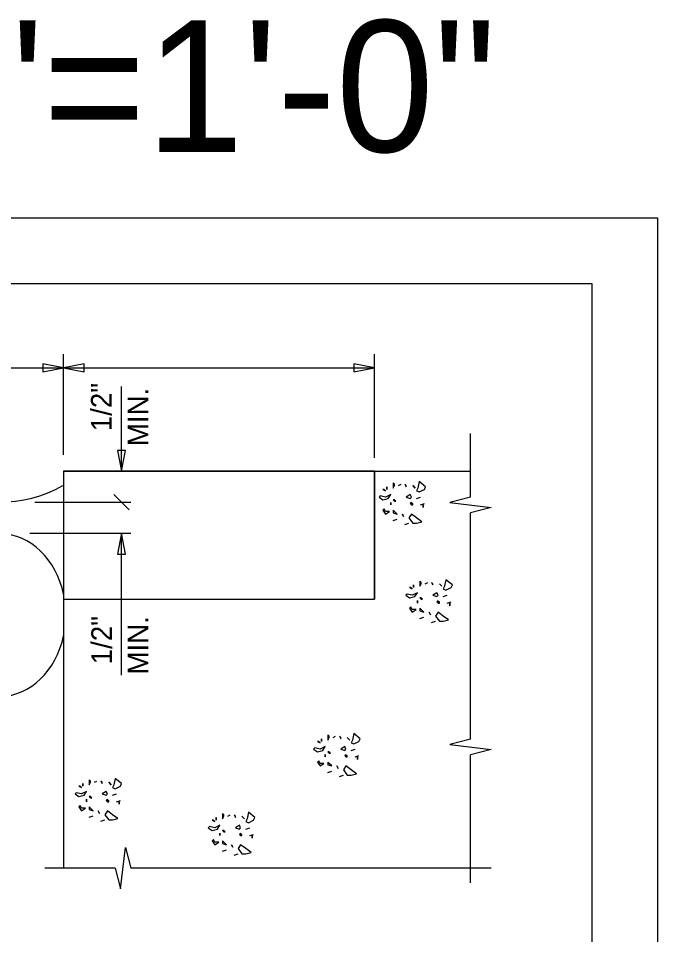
# Model space of a CAD drawing. Extents: x 0 to 11.3, y 0 to 7.8.
# Drawn here: x 9.714 to 11.333, y 5.517 to 7.838 of the extents above; entities that cross this region are included whole.
import ezdxf

# ---------------------------------------------------------------- set-up
doc = ezdxf.new("R2010")
doc.units = 0
for name, color, linetype in [('BORDER_ANNO_Cutsheet', 7, 'Continuous'), ('BRDG_ANNO_Anno-Sheet', 7, 'Continuous'), ('BRDG_ANNO_General-Notes', 7, 'Continuous'), ('BRDG_BASE_Obj-Line', 7, 'Continuous'), ('BRDG_BASE_Pattern', 7, 'Continuous')]:
    doc.layers.add(name, color=color, linetype=linetype)

msp = doc.modelspace()

# ---------------------------------------------------------------- linework, layer by layer
at = {"layer": 'BORDER_ANNO_Cutsheet'}
msp.add_lwpolyline([(0, 7.3333), (11.3333, 7.3333), (11.3333, 0), (0, 0)], close=True, dxfattribs=at)
at = {"layer": 'BRDG_ANNO_Anno-Sheet'}
msp.add_lwpolyline([(0.5, 7.1667), (11.1667, 7.1667), (11.1667, 0.1667), (0.5, 0.1667)], close=True, dxfattribs=at)
at = {"layer": 'BRDG_ANNO_General-Notes'}
for p, q in [((9.8291, 6.7329), (9.8291, 6.9872)), ((10.6164, 6.7246), (10.6164, 6.9872)), ((9.5051, 6.9529), (9.8291, 6.9529)), ((9.829, 6.953), (9.7765, 6.9628)), ((9.7765, 6.9628), (9.7765, 6.9431)), ((9.7765, 6.9431), (9.829, 6.953)), ((9.8815, 6.9628), (9.829, 6.953)), ((9.829, 6.953), (9.8815, 6.9431)), ((9.8291, 6.9529), (10.6164, 6.9529)), ((9.8815, 6.9431), (9.8815, 6.9628)), ((10.6162, 6.953), (10.5638, 6.9628)), ((10.5638, 6.9628), (10.5638, 6.9431)), ((10.5638, 6.9431), (10.6162, 6.953)), ((9.9756, 6.6912), (9.9756, 6.906)), ((9.9855, 6.7437), (9.9658, 6.7437)), ((9.9658, 6.7437), (9.9756, 6.6912)), ((9.9756, 6.6912), (9.9855, 6.7437)), ((9.9756, 6.6125), (9.9563, 6.6318)), ((9.7565, 6.6125), (9.9989, 6.6125)), ((9.995, 6.5931), (9.9756, 6.6125)), ((9.7437, 6.5337), (9.9989, 6.5337)), ((9.9756, 6.5337), (9.9658, 6.4813)), ((9.9756, 6.1746), (9.9756, 6.5337)), ((9.9855, 6.4813), (9.9756, 6.5337)), ((9.9658, 6.4813), (9.9855, 6.4813))]:
    msp.add_line(p, q, dxfattribs=at)
at = {"layer": 'BRDG_BASE_Obj-Line'}
for p, q in [((10.8597, 6.6253), (10.8597, 6.7864)), ((9.829, 6.6912), (10.6654, 6.6912)), ((9.8291, 6.6912), (10.8598, 6.6912)), ((9.8291, 6.6912), (9.8291, 5.6855)), ((10.6164, 6.6912), (10.6164, 6.3671)), ((10.8597, 6.6253), (10.8072, 6.6121)), ((10.8072, 6.6121), (10.9121, 6.599)), ((10.9121, 6.599), (10.8597, 6.5859)), ((10.8597, 6.0122), (10.8597, 6.5859)), ((9.8291, 6.3671), (10.6164, 6.3671)), ((10.8597, 6.0122), (10.8072, 5.9991)), ((10.8072, 5.9991), (10.9121, 5.9859)), ((10.9121, 5.9859), (10.8597, 5.9728)), ((10.8597, 5.6484), (10.8597, 5.9728)), ((9.973, 5.633), (9.9861, 5.738)), ((9.9861, 5.738), (9.9993, 5.6855)), ((9.9599, 5.6855), (9.7818, 5.6855)), ((9.9599, 5.6855), (9.973, 5.633)), ((10.9121, 5.6855), (9.9993, 5.6855))]:
    msp.add_line(p, q, dxfattribs=at)
msp.add_arc((9.666, 6.9425), 0.3299, 240.6646, 299.3018, dxfattribs=at)
for start_param, end_param in [(4.971289, 7.548008), (1.87677, 4.453489)]:
    msp.add_ellipse((9.666, 6.3267), major_axis=(0, 0.2063), ratio=0.818182, start_param=start_param, end_param=end_param, dxfattribs=at)
at = {"layer": 'BRDG_BASE_Pattern'}
for p, q in [((10.6769, 6.6548), (10.6835, 6.6581)), ((10.7229, 6.622), (10.7327, 6.6253)), ((10.7327, 6.6056), (10.7426, 6.6089)), ((10.6639, 6.5663), (10.6737, 6.5695)), ((10.6933, 6.5564), (10.7032, 6.5597)), ((10.7445, 6.4061), (10.7511, 6.4094)), ((10.7905, 6.3733), (10.8003, 6.3766)), ((10.8003, 6.3569), (10.8102, 6.3602)), ((10.7314, 6.3176), (10.7412, 6.3209)), ((10.7609, 6.3078), (10.7708, 6.311)), ((10.5113, 6.0165), (10.5179, 6.0197)), ((10.5572, 5.9836), (10.5671, 5.9869)), ((10.5671, 5.9672), (10.5769, 5.9705)), ((10.4982, 5.9279), (10.508, 5.9311)), ((10.5277, 5.918), (10.5376, 5.9213)), ((9.9071, 5.903), (9.9136, 5.9062)), ((9.953, 5.8702), (9.9628, 5.8734)), ((9.9628, 5.8537), (9.9727, 5.857)), ((9.894, 5.8144), (9.9038, 5.8177)), ((9.9235, 5.8045), (9.9333, 5.8078)), ((10.2446, 5.817), (10.2512, 5.8203)), ((10.2905, 5.7842), (10.3004, 5.7875)), ((10.3004, 5.7678), (10.3102, 5.7711)), ((10.2315, 5.7284), (10.2414, 5.7317)), ((10.261, 5.7186), (10.2708, 5.7219))]:
    msp.add_line(p, q, dxfattribs=at)
for points in [[(9.829, 6.3671), (10.6163, 6.3671), (10.6163, 6.6912), (9.829, 6.6912)], [(10.7261, 6.6482), (10.7229, 6.6417), (10.7294, 6.6384), (10.7426, 6.6449), (10.7458, 6.6515), (10.7294, 6.6646)], [(10.6376, 6.6449), (10.6442, 6.6417), (10.6409, 6.6449)], [(10.6474, 6.6449), (10.6474, 6.6515)], [(10.6639, 6.6548), (10.6639, 6.6482), (10.6671, 6.6548), (10.6671, 6.6581), (10.6639, 6.6614)], [(10.6933, 6.6581), (10.6966, 6.6515), (10.6966, 6.6548), (10.6966, 6.6548), (10.6966, 6.6548), (10.6966, 6.6548), (10.6933, 6.6581), (10.6933, 6.6581)], [(10.7196, 6.6482), (10.713, 6.6548)], [(10.6278, 6.6253), (10.6376, 6.6187), (10.6507, 6.622), (10.6573, 6.6318), (10.6442, 6.6253), (10.631, 6.6285)], [(10.6671, 6.6154), (10.6704, 6.6154), (10.6704, 6.6154), (10.6704, 6.6154), (10.6704, 6.6154), (10.6671, 6.6187), (10.6671, 6.6187), (10.6639, 6.6187), (10.6639, 6.6187), (10.6671, 6.6154)], [(10.6966, 6.6253), (10.7065, 6.622), (10.7097, 6.6253), (10.7065, 6.6318)], [(10.6376, 6.5924), (10.6442, 6.5826), (10.654, 6.5892), (10.6442, 6.5892), (10.6409, 6.5957)], [(10.6573, 6.6056), (10.6573, 6.6121)], [(10.7097, 6.6056), (10.713, 6.6056), (10.713, 6.6089), (10.713, 6.6089), (10.7097, 6.6089), (10.7097, 6.6089), (10.7097, 6.6121), (10.7097, 6.6121), (10.7097, 6.6121), (10.7065, 6.6089)], [(10.7393, 6.599), (10.7393, 6.6056)], [(10.6639, 6.5859), (10.6737, 6.5826), (10.6737, 6.5826), (10.6671, 6.5892), (10.6639, 6.5924)], [(10.6901, 6.576), (10.6868, 6.5826)], [(10.7032, 6.5728), (10.713, 6.5597), (10.7229, 6.5597), (10.736, 6.563), (10.7229, 6.5728), (10.7097, 6.5826)], [(10.7314, 6.4061), (10.7314, 6.3996), (10.7347, 6.4061), (10.7347, 6.4094), (10.7314, 6.4127)], [(10.7609, 6.4094), (10.7642, 6.4029), (10.7642, 6.4061), (10.7642, 6.4061), (10.7642, 6.4061), (10.7642, 6.4061), (10.7609, 6.4094), (10.7609, 6.4094)], [(10.7937, 6.3996), (10.7905, 6.393), (10.797, 6.3897), (10.8102, 6.3963), (10.8134, 6.4029), (10.797, 6.416)], [(10.7052, 6.3963), (10.7117, 6.393), (10.7084, 6.3963)], [(10.715, 6.3963), (10.715, 6.4029)], [(10.7872, 6.3996), (10.7806, 6.4061)], [(10.6953, 6.3766), (10.7052, 6.3701), (10.7183, 6.3733), (10.7248, 6.3832), (10.7117, 6.3766), (10.6986, 6.3799)], [(10.7248, 6.3569), (10.7248, 6.3635)], [(10.7347, 6.3668), (10.738, 6.3668), (10.738, 6.3668), (10.738, 6.3668), (10.738, 6.3668), (10.7347, 6.3701), (10.7347, 6.3701), (10.7314, 6.3701), (10.7314, 6.3701), (10.7347, 6.3668)], [(10.7642, 6.3766), (10.7741, 6.3733), (10.7773, 6.3766), (10.7741, 6.3832)], [(10.7773, 6.3569), (10.7806, 6.3569), (10.7806, 6.3602), (10.7806, 6.3602), (10.7773, 6.3602), (10.7773, 6.3602), (10.7773, 6.3635), (10.7773, 6.3635), (10.7773, 6.3635), (10.7741, 6.3602)], [(10.7052, 6.3438), (10.7117, 6.334), (10.7216, 6.3405), (10.7117, 6.3405), (10.7084, 6.3471)], [(10.7314, 6.3372), (10.7412, 6.334), (10.7412, 6.334), (10.7347, 6.3405), (10.7314, 6.3438)], [(10.8069, 6.3504), (10.8069, 6.3569)], [(10.7577, 6.3274), (10.7544, 6.334)], [(10.7708, 6.3242), (10.7806, 6.311), (10.7905, 6.311), (10.8036, 6.3143), (10.7905, 6.3242), (10.7773, 6.334)], [(10.4818, 6.0066), (10.4818, 6.0132)], [(10.4982, 6.0165), (10.4982, 6.0099), (10.5015, 6.0165), (10.5015, 6.0197), (10.4982, 6.023)], [(10.5277, 6.0197), (10.531, 6.0132), (10.531, 6.0165), (10.531, 6.0165), (10.531, 6.0165), (10.531, 6.0165), (10.5277, 6.0197), (10.5277, 6.0197)], [(10.554, 6.0099), (10.5474, 6.0165)], [(10.5605, 6.0099), (10.5572, 6.0033), (10.5638, 6.0001), (10.5769, 6.0066), (10.5802, 6.0132), (10.5638, 6.0263)], [(10.4621, 5.9869), (10.4719, 5.9804), (10.4851, 5.9836), (10.4916, 5.9935), (10.4785, 5.9869), (10.4654, 5.9902)], [(10.4719, 6.0066), (10.4785, 6.0033), (10.4752, 6.0066)], [(10.531, 5.9869), (10.5408, 5.9836), (10.5441, 5.9869), (10.5408, 5.9935)], [(10.4916, 5.9672), (10.4916, 5.9738)], [(10.5015, 5.9771), (10.5047, 5.9771), (10.5047, 5.9771), (10.5047, 5.9771), (10.5047, 5.9771), (10.5015, 5.9804), (10.5015, 5.9804), (10.4982, 5.9804), (10.4982, 5.9804), (10.5015, 5.9771)], [(10.5441, 5.9672), (10.5474, 5.9672), (10.5474, 5.9705), (10.5474, 5.9705), (10.5441, 5.9705), (10.5441, 5.9705), (10.5441, 5.9738), (10.5441, 5.9738), (10.5441, 5.9738), (10.5408, 5.9705)], [(10.5736, 5.9607), (10.5736, 5.9672)], [(10.4719, 5.9541), (10.4785, 5.9443), (10.4883, 5.9508), (10.4785, 5.9508), (10.4752, 5.9574)], [(10.4982, 5.9476), (10.508, 5.9443), (10.508, 5.9443), (10.5015, 5.9508), (10.4982, 5.9541)], [(10.5244, 5.9377), (10.5211, 5.9443)], [(10.5376, 5.9344), (10.5474, 5.9213), (10.5572, 5.9213), (10.5704, 5.9246), (10.5572, 5.9344), (10.5441, 5.9443)], [(9.8776, 5.8931), (9.8776, 5.8997)], [(9.894, 5.903), (9.894, 5.8964), (9.8972, 5.903), (9.8972, 5.9062), (9.894, 5.9095)], [(9.9235, 5.9062), (9.9268, 5.8997), (9.9268, 5.903), (9.9268, 5.903), (9.9268, 5.903), (9.9268, 5.903), (9.9235, 5.9062), (9.9235, 5.9062)], [(9.9497, 5.8964), (9.9432, 5.903)], [(9.9563, 5.8964), (9.953, 5.8898), (9.9596, 5.8866), (9.9727, 5.8931), (9.9759, 5.8997), (9.9596, 5.9128)], [(9.8579, 5.8734), (9.8677, 5.8669), (9.8808, 5.8702), (9.8874, 5.88), (9.8743, 5.8734), (9.8611, 5.8767)], [(9.8677, 5.8931), (9.8743, 5.8898), (9.871, 5.8931)], [(9.9268, 5.8734), (9.9366, 5.8702), (9.9399, 5.8734), (9.9366, 5.88)], [(9.8874, 5.8537), (9.8874, 5.8603)], [(9.8972, 5.8636), (9.9005, 5.8636), (9.9005, 5.8636), (9.9005, 5.8636), (9.9005, 5.8636), (9.8972, 5.8669), (9.8972, 5.8669), (9.894, 5.8669), (9.894, 5.8669), (9.8972, 5.8636)], [(9.9399, 5.8537), (9.9432, 5.8537), (9.9432, 5.857), (9.9432, 5.857), (9.9399, 5.857), (9.9399, 5.857), (9.9399, 5.8603), (9.9399, 5.8603), (9.9399, 5.8603), (9.9366, 5.857)], [(9.9694, 5.8472), (9.9694, 5.8537)], [(9.8677, 5.8406), (9.8743, 5.8308), (9.8841, 5.8373), (9.8743, 5.8373), (9.871, 5.8439)], [(9.894, 5.8341), (9.9038, 5.8308), (9.9038, 5.8308), (9.8972, 5.8373), (9.894, 5.8406)], [(9.9202, 5.8242), (9.9169, 5.8308)], [(9.9333, 5.8209), (9.9432, 5.8078), (9.953, 5.8078), (9.9661, 5.8111), (9.953, 5.8209), (9.9399, 5.8308)], [(10.2938, 5.8105), (10.2905, 5.8039), (10.2971, 5.8006), (10.3102, 5.8072), (10.3135, 5.8137), (10.2971, 5.8269)], [(10.2053, 5.8072), (10.2118, 5.8039), (10.2085, 5.8072)], [(10.2151, 5.8072), (10.2151, 5.8137)], [(10.2315, 5.817), (10.2315, 5.8105), (10.2348, 5.817), (10.2348, 5.8203), (10.2315, 5.8236)], [(10.261, 5.8203), (10.2643, 5.8137), (10.2643, 5.817), (10.2643, 5.817), (10.2643, 5.817), (10.2643, 5.817), (10.261, 5.8203), (10.261, 5.8203)], [(10.2872, 5.8105), (10.2807, 5.817)], [(10.1954, 5.7875), (10.2053, 5.7809), (10.2184, 5.7842), (10.2249, 5.7941), (10.2118, 5.7875), (10.1987, 5.7908)], [(10.2348, 5.7777), (10.2381, 5.7777), (10.2381, 5.7777), (10.2381, 5.7777), (10.2381, 5.7777), (10.2348, 5.7809), (10.2348, 5.7809), (10.2315, 5.7809), (10.2315, 5.7809), (10.2348, 5.7777)], [(10.2643, 5.7875), (10.2741, 5.7842), (10.2774, 5.7875), (10.2741, 5.7941)], [(10.2053, 5.7547), (10.2118, 5.7448), (10.2217, 5.7514), (10.2118, 5.7514), (10.2085, 5.758)], [(10.2249, 5.7678), (10.2249, 5.7744)], [(10.2774, 5.7678), (10.2807, 5.7678), (10.2807, 5.7711), (10.2807, 5.7711), (10.2774, 5.7711), (10.2774, 5.7711), (10.2774, 5.7744), (10.2774, 5.7744), (10.2774, 5.7744), (10.2741, 5.7711)], [(10.3069, 5.7612), (10.3069, 5.7678)], [(10.2315, 5.7481), (10.2414, 5.7448), (10.2414, 5.7448), (10.2348, 5.7514), (10.2315, 5.7547)], [(10.2577, 5.7383), (10.2545, 5.7448)], [(10.2708, 5.735), (10.2807, 5.7219), (10.2905, 5.7219), (10.3036, 5.7252), (10.2905, 5.735), (10.2774, 5.7448)]]:
    msp.add_lwpolyline(points, close=True, dxfattribs=at)

# ---------------------------------------------------------------- texts
at = {"layer": 'BRDG_ANNO_Anno-Sheet'}
msp.add_text('3"=1\'-0"', height=0.33333, dxfattribs=at).set_placement((9.3708, 7.5))
at = {"layer": 'BRDG_ANNO_General-Notes'}
for s, height, p in [('1/2"', 0.0525, (9.9509, 6.7922)), ('MIN.', 0.05248, (10.0439, 6.7545)), ('1/2"', 0.0525, (9.9517, 6.2018)), ('MIN.', 0.05248, (10.0439, 6.1759))]:
    msp.add_text(s, height=height, rotation=90, dxfattribs=at).set_placement(p)

doc.saveas('drawing.dxf')
